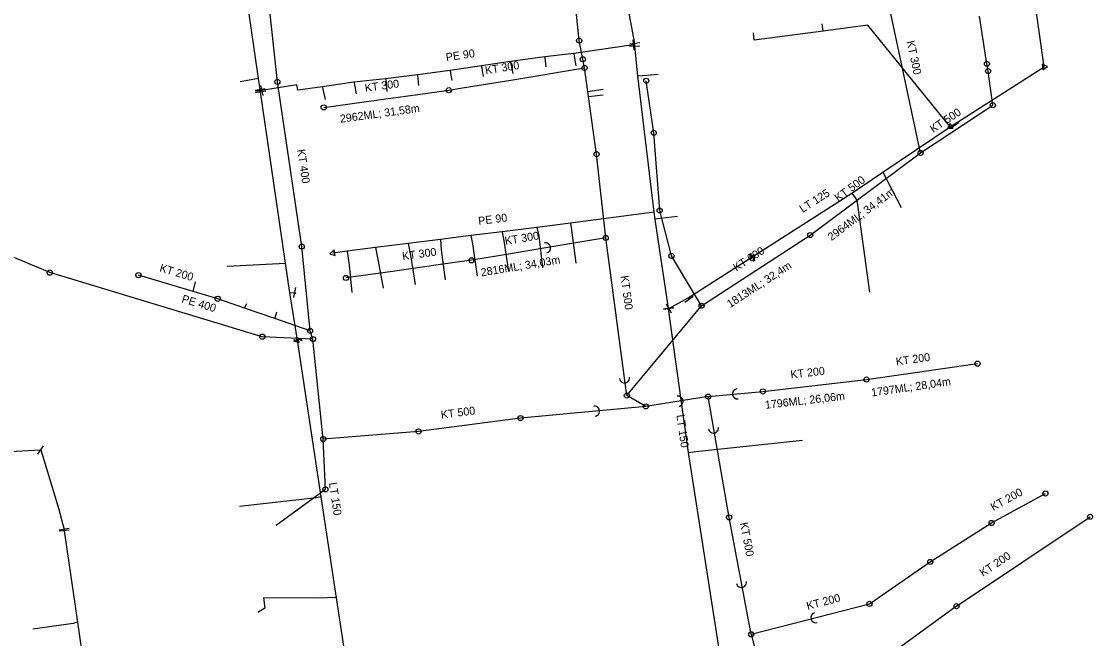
# Model space of a CAD drawing. Extents: x -867696 to -865033, y -1042522 to -1039817.
# Drawn here: x -866610.2 to -866342.2, y -1040244.3 to -1040090 of the extents above; entities that cross this region are included whole.
import ezdxf

# ---------------------------------------------------------------- set-up
doc = ezdxf.new("R2010")
doc.units = 0
for name, color, linetype in [('KN - destova', 7, 'Continuous'), ('KN - jednotna', 7, 'Continuous'), ('KN - ostatni', 7, 'Continuous'), ('KN - popis material', 7, 'Continuous'), ('KN - popis usek delka', 7, 'Continuous'), ('KN - pripojka', 7, 'Continuous'), ('KN - sachta komora', 7, 'Continuous'), ('Level 1', 7, 'Continuous'), ('V - armatura', 7, 'Continuous'), ('V - hydrant', 7, 'Continuous'), ('V - ostatni', 7, 'Continuous'), ('V - popis material', 7, 'Continuous'), ('V - pripojka', 7, 'Continuous'), ('V - rozvadeci', 7, 'Continuous')]:
    doc.layers.add(name, color=color, linetype=linetype)

# ---------------------------------------------------------------- blocks, each defined once
blk = doc.blocks.new('100.M')
at = {"layer": 'Level 1'}
blk.add_circle((0, 0), 1.27, dxfattribs=at)
blk = doc.blocks.new('107')
at = {"layer": 'Level 1'}
blk.add_arc((0, 0), 1.27, 270, 90, dxfattribs=at)
blk = doc.blocks.new('147')
at = {"layer": 'Level 1'}
blk.add_line((0, 1.27), (0, -1.27), dxfattribs=at)
blk = doc.blocks.new('111')
at = {"layer": 'Level 1'}
for p, q in [((0.42, 0.72), (-0.83, 0)), ((-0.83, 0), (0.42, -0.72)), ((0.42, -0.72), (0.42, 0.72))]:
    blk.add_line(p, q, dxfattribs=at)
blk = doc.blocks.new('156')
at = {"layer": 'Level 1'}
for p, q in [((-0.07, 1.04), (-0.68, -0.3)), ((0.28, 1.04), (-0.19, 0.08)), ((-0.19, 0.08), (0.7, 0.29)), ((0.7, 0.29), (0.02, -1.08)), ((-0.68, -0.3), (0.21, -0.09)), ((0.21, -0.09), (-0.28, -1.08))]:
    blk.add_line(p, q, dxfattribs=at)
blk = doc.blocks.new('150')
at = {"layer": 'Level 1'}
blk.add_line((0, 1.27), (0, -1.27), dxfattribs=at)

msp = doc.modelspace()

# ---------------------------------------------------------------- linework, layer by layer
at = {"layer": 'KN - destova'}
for points in [[(-866376.448, -1040236.199), (-866343.094, -1040213.874)], [(-866376.448, -1040236.199), (-866406.008, -1040257.679)]]:
    msp.add_lwpolyline(points, dxfattribs=at)
at = {"layer": 'KN - jednotna'}
for points in [[(-866470.797, -1040094.799), (-866473.763, -1040065.329)], [(-866385.436, -1040122.877), (-866395.498, -1040075.88)], [(-866546.222, -1040105.131), (-866548.186, -1040086.588)], [(-866368.855, -1040100.601), (-866370.701, -1040088.68)], [(-866469.869, -1040099.454), (-866470.797, -1040094.799)], [(-866503.376, -1040107.199), (-866499.469, -1040106.559), (-866495.763, -1040105.953), (-866487.869, -1040104.661), (-866469.447, -1040101.646)], [(-866469.447, -1040101.646), (-866469.869, -1040099.454)], [(-866466.43, -1040123.187), (-866468.445, -1040108.795), (-866468.625, -1040107.517), (-866469.447, -1040101.646)], [(-866368.569, -1040102.447), (-866368.855, -1040100.601)], [(-866367.396, -1040110.97), (-866368.569, -1040102.447)], [(-866540.133, -1040146.294), (-866546.222, -1040105.131)], [(-866534.658, -1040111.491), (-866531.655, -1040111.079), (-866527.571, -1040110.518), (-866519.161, -1040109.364), (-866511.142, -1040108.264), (-866503.376, -1040107.199)], [(-866452.161, -1040117.866), (-866454.016, -1040104.845)], [(-866385.436, -1040122.877), (-866367.396, -1040110.97)], [(-866450.671, -1040137.283), (-866452.161, -1040117.866)], [(-866464.146, -1040144.149), (-866466.43, -1040123.187)], [(-866413.049, -1040143.408), (-866385.436, -1040122.877)], [(-866447.724, -1040148.627), (-866450.671, -1040137.283)], [(-866464.146, -1040144.149), (-866481.118, -1040146.973), (-866489.975, -1040148.447), (-866495.025, -1040149.287), (-866497.711, -1040149.734)], [(-866458.873, -1040183.528), (-866464.146, -1040144.149)], [(-866440.193, -1040161.097), (-866413.049, -1040143.408)], [(-866538.058, -1040167.37), (-866540.133, -1040146.294)], [(-866603.12, -1040152.81), (-866613.82, -1040148.29)], [(-866497.711, -1040149.734), (-866506.043, -1040150.904), (-866509.444, -1040151.382), (-866517.42, -1040152.502), (-866525.334, -1040153.614), (-866529.086, -1040154.141)], [(-866440.193, -1040161.097), (-866447.724, -1040148.627)], [(-866550, -1040168.83), (-866603.12, -1040152.81)], [(-866561.148, -1040159.357), (-866567.271, -1040157.529), (-866580.961, -1040153.443)], [(-866538.058, -1040167.37), (-866546.871, -1040164.311), (-866554.413, -1040161.694), (-866561.148, -1040159.357)], [(-866458.873, -1040183.528), (-866440.193, -1040161.097)], [(-866537.33, -1040169.41), (-866550, -1040168.83)], [(-866537.33, -1040169.41), (-866538.058, -1040167.37)], [(-866534.758, -1040194.418), (-866537.33, -1040169.41)], [(-866398.966, -1040179.543), (-866371.214, -1040175.573)], [(-866424.854, -1040182.525), (-866398.966, -1040179.543)], [(-866454.13, -1040186.252), (-866458.873, -1040183.528)], [(-866438.585, -1040183.814), (-866454.13, -1040186.252)], [(-866438.585, -1040183.814), (-866424.854, -1040182.525)], [(-866433.326, -1040214.023), (-866438.585, -1040183.814)], [(-866454.13, -1040186.252), (-866485.444, -1040189.177)], [(-866485.444, -1040189.177), (-866510.925, -1040192.525)], [(-866510.925, -1040192.525), (-866534.758, -1040194.418)], [(-866534.234, -1040207.02), (-866534.758, -1040194.418)], [(-866367.708, -1040215.413), (-866354.254, -1040208.026)], [(-866427.788, -1040243.249), (-866433.326, -1040214.023)], [(-866383.021, -1040225.133), (-866367.708, -1040215.413)], [(-866398.236, -1040235.643), (-866383.021, -1040225.133)], [(-866427.788, -1040243.249), (-866398.236, -1040235.643)], [(-866427.788, -1040243.249), (-866425.029, -1040254.038)]]:
    msp.add_lwpolyline(points, dxfattribs=at)
at = {"layer": 'KN - pripojka'}
for points in [[(-866468.625, -1040107.517), (-866464.757, -1040106.948)], [(-866468.445, -1040108.795), (-866464.757, -1040108.334)], [(-866567.271, -1040157.529), (-866566.741, -1040155.145)], [(-866554.413, -1040161.694), (-866553.843, -1040160.561)], [(-866546.871, -1040164.311), (-866546.332, -1040162.583)], [(-866534.234, -1040207.02), (-866546.502, -1040216.024)]]:
    msp.add_lwpolyline(points, dxfattribs=at)
at = {"layer": 'V - pripojka'}
for points in [[(-866378.034, -1040116.328), (-866398.62, -1040090.926), (-866409.832, -1040092.457), (-866427.07, -1040094.661)], [(-866409.832, -1040092.457), (-866410.023, -1040090.617)], [(-866427.07, -1040094.661), (-866427.247, -1040092.895)], [(-866479.35, -1040098.88), (-866479.355, -1040099.076), (-866479.16, -1040101.36)], [(-866472.12, -1040098), (-866472.126, -1040098.173), (-866471.61, -1040101.08)], [(-866495.2, -1040101.1), (-866495.182, -1040101.291), (-866494.77, -1040103.79)], [(-866487.96, -1040099.99), (-866487.935, -1040100.16), (-866487.37, -1040102.99)], [(-866550.962, -1040104.31), (-866551.864, -1040104.443), (-866555.496, -1040105.11)], [(-866519.19, -1040104.34), (-866519.16, -1040104.508), (-866518.84, -1040107.49)], [(-866511.21, -1040103.37), (-866511.193, -1040103.527), (-866510.92, -1040106.02)], [(-866503.07, -1040102.25), (-866503.044, -1040102.438), (-866502.65, -1040104.75)], [(-866456.107, -1040103.639), (-866454.867, -1040103.535), (-866451.026, -1040103.192)], [(-866534.97, -1040106.38), (-866534.937, -1040106.523), (-866534.27, -1040109.56)], [(-866527.09, -1040105.21), (-866527.034, -1040105.379), (-866526.56, -1040108.15)], [(-866377.125, -1040115.814), (-866377.026, -1040115.945), (-866376.939, -1040116.091)], [(-866394.875, -1040127.72), (-866390.319, -1040136.502)], [(-866402.595, -1040132.942), (-866401.389, -1040134.674), (-866398.186, -1040157.739)], [(-866451.844, -1040139.394), (-866446.251, -1040138.691)], [(-866481.391, -1040141.491), (-866480.873, -1040143.645), (-866479.931, -1040151.597)], [(-866472.966, -1040140.43), (-866472.771, -1040141.541), (-866471.636, -1040150.412)], [(-866505.467, -1040144.526), (-866505.273, -1040147.112), (-866504.287, -1040154.625)], [(-866497.836, -1040143.564), (-866497.443, -1040145.582), (-866496.256, -1040153.704)], [(-866490.075, -1040142.586), (-866489.618, -1040144.901), (-866488.488, -1040152.519)], [(-866528.798, -1040147.466), (-866528.31, -1040150.963), (-866527.59, -1040157.785)], [(-866521.685, -1040146.57), (-866521.013, -1040149.954), (-866519.822, -1040156.732)], [(-866513.503, -1040145.538), (-866512.981, -1040148.483), (-866511.791, -1040155.81)], [(-866544.171, -1040150.545), (-866558.787, -1040151.256)], [(-866543.102, -1040157.902), (-866541.956, -1040157.765), (-866541.589, -1040157.984)], [(-866443.527, -1040159.134), (-866443.319, -1040159.518), (-866443.287, -1040159.556)], [(-866443.43, -1040197.747), (-866441.638, -1040197.524), (-866414.932, -1040194.723)], [(-866535.256, -1040208.905), (-866536.412, -1040209.154), (-866555.692, -1040211.288)], [(-866531.466, -1040234.076), (-866535.934, -1040234.228), (-866549.685, -1040234.14), (-866549.332, -1040236.74), (-866551.14, -1040237.754)], [(-866596.214, -1040240.235), (-866597.255, -1040240.503), (-866607.346, -1040241.948)]]:
    msp.add_lwpolyline(points, dxfattribs=at)
at = {"layer": 'V - rozvadeci'}
for points in [[(-866354.578, -1040101.362), (-866358.251, -1040075.396), (-866358.843, -1040071.216), (-866360.61, -1040058.726), (-866362.982, -1040041.678), (-866364.257, -1040032.508), (-866364.55, -1040029.89)], [(-866456.9, -1040095.51), (-866459.976, -1040079.013), (-866463.58, -1040054.387), (-866463.766, -1040053.122)], [(-866550.505, -1040107.052), (-866550.962, -1040104.31), (-866555.05, -1040075.918), (-866555.186, -1040074.717)], [(-866457.25, -1040095.85), (-866472.12, -1040098), (-866479.35, -1040098.88), (-866487.96, -1040099.99), (-866495.2, -1040101.1), (-866503.07, -1040102.25), (-866511.21, -1040103.37), (-866519.19, -1040104.34), (-866527.09, -1040105.21), (-866534.97, -1040106.38), (-866541.153, -1040107.157), (-866541.35, -1040105.89), (-866550.19, -1040107.26)], [(-866456.89, -1040095.83), (-866457.25, -1040095.85)], [(-866456.91, -1040096.2), (-866456.89, -1040095.83)], [(-866452.087, -1040137.674), (-866456.107, -1040103.639), (-866456.91, -1040096.2)], [(-866456.89, -1040095.83), (-866456.9, -1040095.51)], [(-866378.034, -1040116.328), (-866377.125, -1040115.814), (-866354.578, -1040101.362)], [(-866550.459, -1040107.325), (-866550.505, -1040107.052)], [(-866550.19, -1040107.26), (-866550.459, -1040107.325)], [(-866550.41, -1040107.62), (-866550.459, -1040107.325)], [(-866528.076, -1040256.593), (-866530.637, -1040239.583), (-866535.256, -1040208.905), (-866541.165, -1040169.659), (-866543.102, -1040157.902), (-866550.41, -1040107.62)], [(-866448.4, -1040161.751), (-866443.527, -1040159.134), (-866402.595, -1040132.942), (-866394.875, -1040127.72), (-866378.034, -1040116.328)], [(-866452.087, -1040137.674), (-866472.966, -1040140.43), (-866481.391, -1040141.491), (-866490.075, -1040142.586), (-866497.836, -1040143.564), (-866505.467, -1040144.526), (-866513.503, -1040145.538), (-866521.685, -1040146.57), (-866528.798, -1040147.466), (-866532.329, -1040147.911)], [(-866448.457, -1040161.717), (-866451.824, -1040139.536), (-866452.087, -1040137.674)], [(-866448.447, -1040161.772), (-866448.457, -1040161.717)], [(-866448.447, -1040161.772), (-866448.4, -1040161.751)], [(-866448.439, -1040161.838), (-866448.447, -1040161.772)], [(-866434.953, -1040252.287), (-866443.43, -1040197.747), (-866448.439, -1040161.838)], [(-866623.78, -1040198.02), (-866617.56, -1040197.9), (-866611.53, -1040197.46), (-866605.39, -1040197.15)], [(-866605.39, -1040197.15), (-866600.94, -1040211.7), (-866599.51, -1040217)], [(-866599.51, -1040217), (-866599.51, -1040217.35)], [(-866599.51, -1040217.35), (-866596.214, -1040240.235), (-866591.714, -1040271.546)]]:
    msp.add_lwpolyline(points, dxfattribs=at)

# ---------------------------------------------------------------- block references
at = {"layer": 'KN - ostatni'}
for p, xscale, yscale, rotation in [((-866479.187, -1040146.652), 1.0073309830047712, 1.0073309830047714, 12.13890866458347), ((-866459.464, -1040179.11), 0.9999999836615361, 0.9999999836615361, -81.99999961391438), ((-866431.21, -1040183.122), 1.0011217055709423, 1.0011217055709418, -173.41739016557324), ((-866446.077, -1040184.989), 1.008377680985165, 1.0083776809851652, 11.626378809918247), ((-866466.97, -1040187.451), 1.0011217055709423, 1.0011217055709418, 6.582609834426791), ((-866437.219, -1040191.661), 0.9999999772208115, 0.9999999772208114, -79.99999971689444), ((-866430.248, -1040230.269), 0.999999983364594, 0.9999999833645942, -78.9999997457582), ((-866411.6, -1040239.083), 0.999999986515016, 0.9999999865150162, -164.99999987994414)]:
    msp.add_blockref('107', p, dxfattribs=dict(at, xscale=xscale, yscale=yscale, rotation=rotation))
at = {"layer": 'KN - sachta komora'}
for p, xscale, yscale, rotation in [((-866470.797, -1040094.799), 0.5000000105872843, 0.5000000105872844, 98.99999960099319), ((-866469.869, -1040099.454), 0.5000000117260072, 0.5000000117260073, 101.99999938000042), ((-866469.447, -1040101.646), 0.49999998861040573, 0.4999999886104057, 100.00000028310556), ((-866368.855, -1040100.601), 0.5000000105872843, 0.5000000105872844, -81.00000039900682), ((-866368.569, -1040102.447), 0.5000000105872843, 0.5000000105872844, 98.99999960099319), ((-866546.222, -1040105.131), 0.49999999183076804, 0.49999999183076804, 98.00000038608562), ((-866454.016, -1040104.845), 0.5000000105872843, 0.5000000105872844, 98.99999960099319), ((-866503.376, -1040107.199), 0.5041888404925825, 0.5041888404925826, -168.37362119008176), ((-866534.658, -1040111.491), 0.5046025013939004, 0.5046025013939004, 11.116918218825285), ((-866367.396, -1040110.97), 0.49999998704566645, 0.49999998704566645, -114.00000060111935), ((-866452.161, -1040117.866), 0.500095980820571, 0.500095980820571, 97.08900113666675), ((-866466.43, -1040123.187), 0.49999999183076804, 0.49999999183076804, 98.00000038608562), ((-866385.436, -1040122.877), 0.4999999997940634, 0.4999999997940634, -110.00000065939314), ((-866450.671, -1040137.283), 0.49999998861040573, 0.4999999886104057, 100.00000028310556), ((-866464.146, -1040144.149), 0.500095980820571, 0.500095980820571, 97.08900113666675), ((-866413.049, -1040143.408), 0.5000000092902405, 0.5000000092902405, -144.99999976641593), ((-866540.133, -1040146.294), 0.49999999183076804, 0.49999999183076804, 98.00000038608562), ((-866497.711, -1040149.734), 0.5041888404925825, 0.5041888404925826, -168.37362119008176), ((-866447.724, -1040148.627), 0.5000000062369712, 0.500000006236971, 112.99999954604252), ((-866603.12, -1040152.81), 0.5158478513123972, 0.5158478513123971, 156.4154111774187), ((-866580.961, -1040153.443), 0.5182729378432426, 0.5182729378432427, 158.02850914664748), ((-866529.086, -1040154.141), 0.5046025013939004, 0.5046025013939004, -168.88308178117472), ((-866561.148, -1040159.357), 0.517562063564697, 0.5175620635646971, 157.49634583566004), ((-866440.193, -1040161.097), 0.5000000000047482, 0.5000000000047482, -137.9999986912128), ((-866550, -1040168.83), 0.5041888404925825, 0.5041888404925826, 168.37362119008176), ((-866538.058, -1040167.37), 0.500095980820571, 0.500095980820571, 97.08900113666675), ((-866537.33, -1040169.41), 0.4999999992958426, 0.4999999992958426, 103.00000027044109), ((-866371.214, -1040175.573), 0.5041888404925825, 0.5041888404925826, 11.626378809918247), ((-866398.966, -1040179.543), 0.5046025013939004, 0.5046025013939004, -168.88308178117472), ((-866424.854, -1040182.525), 0.5005608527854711, 0.5005608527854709, -173.41739016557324), ((-866458.873, -1040183.528), 0.4999999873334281, 0.499999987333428, 124.00000045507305), ((-866438.585, -1040183.814), 0.5000000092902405, 0.5000000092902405, 144.99999976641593), ((-866454.13, -1040186.252), 0.5046025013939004, 0.5046025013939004, -168.88308178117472), ((-866485.444, -1040189.177), 0.5049058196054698, 0.5049058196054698, -169.38969821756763), ((-866510.925, -1040192.525), 0.5049058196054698, 0.5049058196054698, -169.38969821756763), ((-866534.758, -1040194.418), 0.500000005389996, 0.5000000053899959, 141.00000108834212), ((-866534.234, -1040207.02), 0.4999999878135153, 0.49999998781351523, 93.00000001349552), ((-866354.254, -1040208.026), 0.5018521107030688, 0.5018521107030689, 29.379208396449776), ((-866433.326, -1040214.023), 0.499999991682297, 0.4999999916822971, 101.0000002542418), ((-866343.094, -1040213.874), 0.4999999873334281, 0.499999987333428, 34.00000045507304), ((-866367.708, -1040215.413), 0.5000000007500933, 0.5000000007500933, -149.00000017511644), ((-866383.021, -1040225.133), 0.4999999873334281, 0.499999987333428, -145.99999954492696), ((-866398.236, -1040235.643), 0.5084781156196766, 0.5084781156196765, -153.02398354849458), ((-866376.448, -1040236.199), 0.5000000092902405, 0.5000000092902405, -144.99999976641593), ((-866427.788, -1040243.249), 0.4999999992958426, 0.4999999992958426, 103.00000027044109)]:
    msp.add_blockref('100.M', p, dxfattribs=dict(at, xscale=xscale, yscale=yscale, rotation=rotation))
at = {"layer": 'V - armatura'}
for p, xscale, yscale, rotation in [((-866456.91, -1040096.2), 1.00000001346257, 1.0000000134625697, -88.00000009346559), ((-866456.9, -1040095.51), 1.000191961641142, 1.000191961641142, -82.91099886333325), ((-866457.25, -1040095.85), 1.0011217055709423, 1.0011217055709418, 6.582609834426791), ((-866550.505, -1040107.052), 0.9999999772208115, 0.9999999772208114, -79.99999971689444), ((-866550.459, -1040107.325), 0.9999999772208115, 0.9999999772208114, -79.99999971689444), ((-866550.19, -1040107.26), 1.0045862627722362, 1.0045862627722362, 13.174090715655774), ((-866550.41, -1040107.62), 1.0000000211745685, 1.0000000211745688, -81.00000039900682), ((-866448.4, -1040161.751), 1.0106518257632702, 1.0106518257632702, 28.16211573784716), ((-866448.457, -1040161.717), 0.9999999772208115, 0.9999999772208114, -79.99999971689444), ((-866448.447, -1040161.772), 1.0000000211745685, 1.0000000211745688, -81.00000039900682), ((-866448.439, -1040161.838), 0.9999999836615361, 0.9999999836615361, -81.99999961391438), ((-866605.39, -1040197.15), 1.000000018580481, 1.000000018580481, 144.99999976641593), ((-866599.51, -1040217), 0.9999999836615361, 0.9999999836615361, -81.99999961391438), ((-866599.51, -1040217.35), 1.000000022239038, 1.0000000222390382, -85.00000001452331)]:
    msp.add_blockref('147', p, dxfattribs=dict(at, xscale=xscale, yscale=yscale, rotation=rotation))
at = {"layer": 'V - hydrant'}
for p, xscale, yscale, rotation in [((-866377.026, -1040115.945), 0.9999999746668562, 0.999999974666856, 124.00000045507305), ((-866541.956, -1040157.765), 1.0060666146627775, 1.0060666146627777, -12.654735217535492), ((-866443.319, -1040159.518), 1.000000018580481, 1.000000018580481, -54.99999976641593)]:
    msp.add_blockref('150', p, dxfattribs=dict(at, xscale=xscale, yscale=yscale, rotation=rotation))
at = {"layer": 'V - ostatni'}
for name, p, xscale, yscale, rotation in [('111', (-866354.578, -1040101.362), 0.9999999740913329, 0.9999999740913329, 65.99999939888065), ('111', (-866378.034, -1040116.328), 0.9999999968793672, 0.9999999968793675, 32.00000027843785), ('111', (-866532.329, -1040147.911), 1.0092050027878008, 1.0092050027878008, 11.116918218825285), ('156', (-866427.593, -1040148.938), 0.9999999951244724, 0.9999999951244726, 33.000001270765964), ('156', (-866541.165, -1040169.659), 1.0000000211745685, 1.0000000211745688, 98.99999960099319)]:
    msp.add_blockref(name, p, dxfattribs=dict(at, xscale=xscale, yscale=yscale, rotation=rotation))

# ---------------------------------------------------------------- texts
at = {"layer": 'KN - popis material'}
for s, rotation, p in [('KT 300', 282.08, (-866388.944, -1040095.026)), ('KT 300', 9.29, (-866494.143, -1040103.255)), ('KT 300', 7.81, (-866524.236, -1040107.639)), ('KT 500', 33.42, (-866382.305, -1040117.934)), ('KT 400', 278.41, (-866541.285, -1040122.101)), ('KT 500', 36.63, (-866406.017, -1040135.189)), ('KT 300', 9.45, (-866489.22, -1040145.889)), ('KT 300', 8, (-866514.893, -1040149.724)), ('KT 600', 33.09, (-866431.494, -1040152.563)), ('KT 200', 343.38, (-866575.823, -1040152.472)), ('KT 500', 277.63, (-866460.452, -1040153.659)), ('PE 400', 343.22, (-866570.309, -1040160.199)), ('KT 200', 8.14, (-866391.491, -1040176.049)), ('KT 200', 6.57, (-866417.857, -1040179.302)), ('KT 500', 7.49, (-866505.231, -1040189.357)), ('KT 200', 28.77, (-866367.286, -1040212.443)), ('KT 500', 280.73, (-866430.617, -1040215.427)), ('KT 200', 33.8, (-866369.855, -1040228.899)), ('KT 200', 14.43, (-866413.685, -1040237.14))]:
    msp.add_text(s, height=2, rotation=rotation, dxfattribs=at).set_placement(p)
at = {"layer": 'KN - popis usek delka'}
for s, rotation, p in [('2962ML; 31,58m', 7.81, (-866530.446, -1040115.353)), ('2964ML; 34,41m', 36.63, (-866407.739, -1040144.942)), ('2816ML; 34,03m', 9.45, (-866495.207, -1040153.778)), ('1813ML; 32,4m', 33.09, (-866433.06, -1040161.699)), ('1797ML; 28,04m', 8.14, (-866397.656, -1040183.8)), ('1796ML; 26,06m', 6.57, (-866424.232, -1040186.882))]:
    msp.add_text(s, height=1.99999, rotation=rotation, dxfattribs=at).set_placement(p)
at = {"layer": 'V - popis material'}
for s, rotation, p in [('PE 90', 8.31, (-866503.976, -1040099.956)), ('LT 125', 32.61, (-866414.943, -1040137.921)), ('PE 90', 7.18, (-866495.9, -1040140.901)), ('LT 150', 277.94, (-866446.484, -1040188.438)), ('LT 150', 278.56, (-866533.357, -1040205.393))]:
    msp.add_text(s, height=2, rotation=rotation, dxfattribs=at).set_placement(p)

doc.saveas('drawing.dxf')
